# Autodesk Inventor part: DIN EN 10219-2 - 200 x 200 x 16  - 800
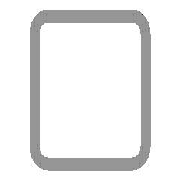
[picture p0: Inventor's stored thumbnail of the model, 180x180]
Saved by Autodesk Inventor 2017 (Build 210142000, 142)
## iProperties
Created: 2016-02
Part Number: DIN EN 10219-2 - 200 x 200 x 16  - 800
Material: Steel, Mild
Description: Cold formed welded structural hollow sections of non-alloy and fine grain structural steel
Document SubType Name: Modeling
Standard: DIN
Designer: iusti
Standard Revision: 2006-07
Standards Organization: DIN
Language: en-US
Size Designation: 200 x 200 x 16
Categories: <MemberInstance><Categories><Category DisplayName="Structural Shapes" InternalName="089c4875-fa83-4c05-b084-43b9cc11f5ed" Mnemonic="GRDR"><CategoryParameter Dis
Stock Number: 200 x 200 x 16
Mass: 67053.1 g
Surface Area: 10890.8 cm^2
Volume: 8541.79 cm^3
Density: 7.85 g/cm^3
Appearance: Semi-Polished
IsCustomPart: 1
_CCFamilyMember: 103
_CCFamilyDisplayName: DIN EN 10219-2 (Square Hollow Section - Cold Formed) - Cold formed welded structural hollow sections of non-alloy and fine grain structural steel
_FrameMemberDoc: Frame Member File
_Version: 15.0.0
_GetPNFromCC: 1
Author: iusti
G_L: 800.000 mm
G_W: 200.000 mm
G_H: 200.000 mm
+25E8C026-FEE3-4A01-9593-771C732A64D6+CUTDETAIL1: Cut
+634D56CB-A472-4F3D-9CA9-6F5BA560080E+CUTDETAIL2: Cut
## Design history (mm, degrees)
node "Start plane"
node "End plane"
sketch "Sketch"
  geometry: L1 (-100, -52)-(-100, 52); L2 (-52, 100)-(52, 100); L3 (100, 52)-(100, -52); L4 (52, -100)-(-52, -100); L5 (-52, 84)-(52, 84); L6 (84, 52)-(84, -52); L7 (52, -84)-(-52, -84); L8 (-84, -52)-(-84, 52); L9 (0, 153.918)-(0, -153.918) reference; L10 (-153.918, 0)-(153.918, 0) reference; A1 r 48 centre (-52, -52) between (-100, -52) and (-52, -100); A2 r 48 centre (-52, 52) between (-52, 100) and (-100, 52); A3 r 48 centre (52, 52) between (100, 52) and (52, 100); A4 r 48 centre (52, -52) between (52, -100) and (100, -52); A5 r 32 centre (-52, 52) between (-52, 84) and (-84, 52); A6 r 32 centre (52, 52) between (84, 52) and (52, 84); A7 r 32 centre (52, -52) between (52, -84) and (84, -52); A8 r 32 centre (-52, -52) between (-84, -52) and (-52, -84)
  constraints: 16 end point, 16 point on circle, 8 centre point, 8 tangent, 4 parallel, 3 equal radius, 2 perpendicular, 7 other
  dimensions: "d7" = 48 radius of A1 (= G_IR); "d10" = 200 distance between parallel lines of L2 L4 (= G_H); "d11" = 200 distance between parallel lines of L1 L3 (= G_W); "d12" = 16 distance between parallel lines of L3 L6 (= G_T); "d15" = 100 distance between parallel lines of L2 L10 (= 0.5 x d10); "d16" = 100 distance between parallel lines of L9 L3 (= 0.5 x d11)
extrude "Body" new body sketch "Sketch" stored distance "d3" = 800 (= G_L); taper "d4" = 0 deg
node "Driven Length"
  sketch "Sketch3"
    geometry: L1 (0, 0)-(10, 0) reference
    constraints: 2 end point, 1 horizontal
  workplane "Work Plane3"
  sketch "Sketch4"
    geometry: L1 (-2, 100)-(12, 100) reference; L2 (-2, 900)-(12, 900) reference
    dimensions: "d18" = 800 distance between parallel lines of L1 L2 (derived)
workplane "Work Plane4"
split "Split1"
workplane "Work Plane5"
split "Split2"
body "Solid1"
other parameters: "G_W" = 200 [user parameter; used in 1 equation term], "G_H" = 200 [user parameter; used in 1 equation term], "G_T" = 16 [user parameter; used in 1 equation term], "G_IR" = 48 [user parameter; used in 1 equation term], "G_L" = 800 (= d18) [user parameter; used in 1 equation term], "d17" = 90 deg
